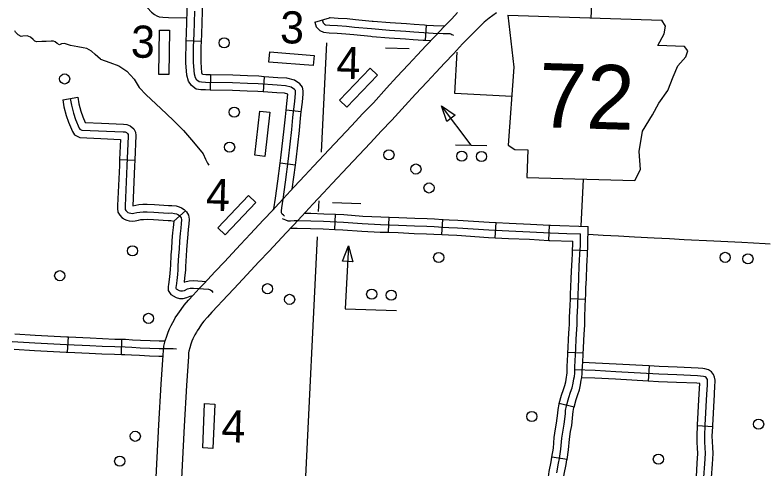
# Model space of a CAD drawing. Extents: x 653372 to 905732, y 627442 to 787275.
# Drawn here: x 676960 to 684356, y 769532 to 774006 of the extents above; entities that cross this region are included whole.
import ezdxf

# ---------------------------------------------------------------- set-up
doc = ezdxf.new("R2010")
doc.units = 0
for name, color, linetype in [('10', 7, 'Continuous'), ('21', 7, 'Continuous'), ('32', 7, 'Continuous'), ('33', 7, 'Continuous'), ('34', 7, 'Continuous'), ('35', 7, 'Continuous'), ('45', 7, 'Continuous'), ('5', 7, 'Continuous'), ('56', 7, 'Continuous'), ('6', 7, 'Continuous')]:
    doc.layers.add(name, color=color, linetype=linetype)

msp = doc.modelspace()

# ---------------------------------------------------------------- linework, layer by layer
at = {"layer": '10'}
for points in [[(678353, 769452.5), (678379.4, 769968.5), (678402.3, 770369), (678421, 770653.3), (678423.3, 770701.2), (678429.1, 770741), (678442, 770793.3), (678456.6, 770839.6), (678470.3, 770879.4), (678484.2, 770913), (678499.1, 770946.4), (678516.1, 770976.2), (678528.8, 770998.5), (678540.4, 771020.9), (678564.7, 771058.2), (678596.9, 771104), (678628.5, 771146.7), (678671.1, 771195.3), (678718.1, 771245.7), (678777.3, 771309.9), (678821.6, 771356.5), (678935.3, 771477.2), (679024.5, 771573.2), (679182.5, 771742.8), (679282.2, 771848.8), (679407.6, 771983.9), (679504.1, 772085.6), (679526.2, 772109.1), (679603.8, 772193.8), (679713.6, 772311.7), (679819.4, 772425), (679904.8, 772515.3), (680057.9, 772678.9), (680166.9, 772796), (680282.7, 772917.9), (680388.1, 773031.6), (680493.9, 773141.1), (680624, 773283.8), (680726.1, 773395.9), (680840.6, 773517.9), (680925.7, 773609.4), (681015.8, 773706.5), (681101.8, 773795.9), (681192.8, 773893.9), (681267.1, 773968.3), (681325, 774029.1)], [(681708.4, 774028.1), (681671.5, 774001.8), (681636.1, 773973.9), (681588.2, 773933.9), (681559.1, 773908.4), (681503, 773853.5), (681446, 773793.8), (681373, 773720.5), (681283.5, 773624.1), (681197.5, 773534.7), (681108.8, 773439.2), (681023.2, 773347.3), (680909.6, 773226.1), (680808.7, 773115.4), (680676.2, 772970), (680569.7, 772859.8), (680465, 772746.8), (680349, 772624.7), (680240.7, 772508.3), (680086.8, 772344), (680001.6, 772253.8), (679896.5, 772141.2), (679787.4, 772024.1), (679709.4, 771939), (679685.8, 771913.9), (679589.9, 771812.9), (679464.9, 771678.1), (679365, 771571.9), (679207.5, 771402.9), (679117.9, 771306.4), (679003.1, 771184.6), (678959.7, 771139), (678901.4, 771075.8), (678856.6, 771027.7), (678823.4, 770989.7), (678799.7, 770957.7), (678771.7, 770918), (678756.8, 770895), (678748.5, 770879.1), (678733.3, 770852.4), (678722.3, 770833.1), (678713.9, 770814.2), (678704.2, 770790.9), (678694, 770761.2), (678682.8, 770725.7), (678674.7, 770692.8), (678672.4, 770676.8), (678670.6, 770639.1), (678651.8, 770353.6), (678629, 769955), (678602.6, 769439.1)]]:
    msp.add_lwpolyline(points, dxfattribs=at)
at = {"layer": '21'}
for p, q in [((681819.5, 774002.5), (681880.4, 773492.9)), ((683373.5, 773896.6), (683340.2, 773956.1)), ((683362.8, 773820.8), (683373.5, 773896.6)), ((683300, 773704.2), (683362.8, 773820.8)), ((683562.1, 773696.3), (683300, 773704.2)), ((683594.7, 773653), (683562.1, 773696.3)), ((683497.1, 773503.6), (683576, 773594.4)), ((683576, 773594.4), (683594.7, 773653)), ((681880.4, 773492.9), (681823.5, 772724.5)), ((683451.5, 773395), (683497.1, 773503.6)), ((683396.7, 773261.2), (683451.5, 773395)), ((683308.4, 773136.9), (683396.7, 773261.2)), ((683245.6, 773020.3), (683308.4, 773136.9)), ((683147.8, 772862.5), (683245.6, 773020.3)), ((683116.3, 772660.3), (683147.8, 772862.5)), ((681823.5, 772724.5), (681889.8, 772680.2)), ((681889.8, 772680.2), (682016.7, 772676.4)), ((682016.7, 772676.4), (682008.5, 772405.9)), ((683127.9, 772482.3), (683116.3, 772660.3)), ((683073.9, 772373.9), (683127.9, 772482.3)), ((682008.5, 772405.9), (683073.9, 772373.9))]:
    msp.add_line(p, q, dxfattribs=at)
msp.add_lwpolyline([(681819.5, 774002.5), (683340.2, 773956.1)], dxfattribs=at)
at = {"layer": '32'}
for p, q in [((678798.9, 773745.3), (678649, 773751.6)), ((678886.7, 773416), (678883.5, 773266)), ((679418.1, 773397.3), (679407.4, 773247.7)), ((679782.9, 773052.8), (679633.8, 773069.2)), ((679724.5, 772526.4), (679575.8, 772546.1)), ((680114.7, 771892.3), (680122, 772042.1)), ((680642.9, 771864.4), (680648.2, 772014.3)), ((681168.3, 771842), (681177.7, 771991.7)), ((681696.1, 771810.6), (681704, 771960.4)), ((682223.1, 771784.7), (682231.7, 771934.5)), ((682607.7, 771681.5), (682457.9, 771689.4)), ((682586.8, 771201.2), (682436.9, 771207.4)), ((677479, 770683.4), (677486.2, 770833.3)), ((678008.4, 770661.4), (678011.9, 770811.4)), ((682562.9, 770673.5), (682413.1, 770680.3)), ((682472.9, 770141.1), (682327.7, 770178.6)), ((682403.5, 769625.4), (682255.3, 769648.8))]:
    msp.add_line(p, q, dxfattribs=at)
for points in [[(678649, 773751.6), (678652, 773822.6), (678658.3, 774045.4), (678661.5, 774150.2), (678666.5, 774279)], [(678798.9, 773745.3), (678802, 773817.3), (678808.3, 774041.1), (678811.4, 774145.1), (678816.4, 774273.3)], [(679725.4, 773261), (679717.5, 773271.3), (679683.7, 773293.4), (679628.5, 773308.2), (679545.6, 773313), (679358.9, 773326.4), (679251.2, 773331.2), (679105.5, 773336.3), (678839.1, 773342), (678800.4, 773343.2), (678777.2, 773347), (678753.7, 773364), (678738.8, 773385.4), (678729.1, 773423.7), (678720.8, 773536.5), (678720.4, 773601.8), (678721.6, 773693.3), (678727, 773819.9), (678733.3, 774043.3)], [(678883.5, 773266), (678837.2, 773267), (678793.1, 773268.3), (678747.6, 773275.8), (678699.4, 773310.7), (678669.4, 773353.8), (678654.7, 773411.7), (678645.8, 773533.6), (678645.4, 773602), (678646.7, 773695.4), (678649, 773751.6)], [(678886.7, 773416), (678841.1, 773417), (678807.9, 773418), (678803.4, 773435.8), (678795.8, 773539.5), (678795.4, 773601.5), (678796.6, 773691.2), (678798.9, 773745.3)], [(679418.1, 773397.3), (679363.3, 773401.3), (679254.2, 773406.1), (679107.6, 773411.3), (678886.7, 773416)], [(679782.9, 773052.8), (679793.4, 773147.9), (679801.8, 773228.1), (679802.8, 773259.2), (679794.8, 773293.7), (679769.3, 773327.1), (679714.6, 773362.7), (679640.5, 773382.6), (679550.4, 773387.9), (679418.1, 773397.3)], [(679407.4, 773247.7), (679354.6, 773251.5), (679248.2, 773256.2), (679103.3, 773261.4), (678883.5, 773266)], [(679633.8, 773069.2), (679644.3, 773164), (679650.6, 773224.6), (679616.4, 773233.8), (679540.7, 773238.2), (679407.4, 773247.7)], [(679617.8, 772024.1), (679606.8, 772033.1), (679596.1, 772044.4), (679589.1, 772057.2), (679586.5, 772077.2), (679590.5, 772104.9), (679602.8, 772191.5), (679626.5, 772357.9), (679657.1, 772588.6), (679689.8, 772876.9), (679701.1, 772995.2), (679718.8, 773156), (679726.9, 773233.1), (679727.5, 773251.8), (679725.4, 773261)], [(679575.8, 772546.1), (679582.7, 772597.7), (679615.2, 772884.7), (679626.5, 773002.9), (679633.8, 773069.2)], [(679724.5, 772526.4), (679731.5, 772579.4), (679764.4, 772869.1), (679775.7, 772987.6), (679782.9, 773052.8)], [(679513.4, 772095.2), (679528.6, 772202), (679552.2, 772368.1), (679575.8, 772546.1)], [(679693.1, 772289.8), (679724.5, 772526.4)], [(679814.8, 772053.6), (679877.9, 772052.6), (680004.5, 772047.8), (680122, 772042.1)], [(680122, 772042.1), (680203.5, 772038.2), (680389, 772024.4), (680567.8, 772017.2), (680648.2, 772014.3)], [(679594.9, 771999.8), (679626.1, 771986), (679649.7, 771978), (679676.2, 771978.1), (679712, 771980.7), (679745, 771979.7), (679875.9, 771977.6), (680001.3, 771972.9), (680198.9, 771963.3), (680384.7, 771949.5), (680564.9, 771942.2), (680742.5, 771936), (680899.8, 771928.5), (681021.6, 771924.9), (681094.5, 771921.7), (681178.6, 771916.5), (681238, 771912.9), (681322.2, 771909.4), (681632.3, 771889.1), (681830.8, 771878.6), (682038.5, 771870.5), (682237, 771859), (682402.9, 771853.1), (682536.9, 771850.9)], [(680648.2, 772014.3), (680745.6, 772010.9), (680902.7, 772003.5), (681024.3, 771999.8), (681098.4, 771996.6), (681177.7, 771991.7)], [(681177.7, 771991.7), (681183.2, 771991.3), (681241.8, 771987.8), (681326.2, 771984.3), (681636.8, 771964), (681704, 771960.4)], [(679678.9, 771906.6), (679743.3, 771904.7), (679873.9, 771902.6), (679998.1, 771898), (680114.7, 771892.3)], [(680114.7, 771892.3), (680194.3, 771888.4), (680380.4, 771874.6), (680562.1, 771867.3), (680642.9, 771864.4)], [(681704, 771960.4), (681834.3, 771953.5), (682042.1, 771945.4), (682231.7, 771934.5)], [(682231.7, 771934.5), (682240.5, 771934), (682612.8, 771920.7)], [(682610.2, 771727.8), (682610.4, 771733.1), (682612.8, 771920.7)], [(680642.9, 771864.4), (680739.4, 771861), (680896.9, 771853.6), (681018.8, 771849.9), (681090.5, 771846.8), (681168.3, 771842)], [(681168.3, 771842), (681174, 771841.6), (681234.2, 771837.9), (681318.2, 771834.5), (681627.9, 771814.2), (681696.1, 771810.6)], [(682387.6, 770075.6), (682389.7, 770108.3), (682398.6, 770153.2), (682420.4, 770237.7), (682438.5, 770290.5), (682453.4, 770333.3), (682464.1, 770376.8), (682471.1, 770420.8), (682477, 770444.6), (682479.4, 770477.4), (682479.7, 770509.5), (682481.2, 770538.5), (682487.1, 770657), (682489.9, 770719.5), (682494.5, 770810.6), (682500.8, 770911.3), (682503, 770952.6), (682504.3, 771026.9), (682509.1, 771138.7), (682514.1, 771258.6), (682515.8, 771316.8), (682520.5, 771410.8), (682524.8, 771538.3), (682527.7, 771587.1), (682531.1, 771651.9), (682535.5, 771735.6), (682536.9, 771850.9)], [(681696.1, 771810.6), (681827.4, 771803.6), (682034.9, 771795.6), (682223.1, 771784.7)], [(682223.1, 771784.7), (682233.5, 771784.1), (682462.5, 771776)], [(682436.9, 771207.4), (682439.1, 771261.2), (682440.9, 771319.8), (682445.6, 771413.9), (682449.9, 771541.8), (682452.8, 771591.3), (682456.2, 771655.9), (682462.5, 771776)], [(682586.8, 771201.2), (682589, 771255.9), (682590.8, 771313.8), (682595.5, 771407.6), (682599.8, 771534.8), (682602.6, 771583), (682606, 771648), (682610.2, 771727.8)], [(682413.1, 770680.3), (682415, 770723), (682419.6, 770814.8), (682426, 770915.6), (682428.1, 770955.2), (682429.3, 771029.1), (682434.2, 771141.9), (682436.9, 771207.4)], [(682562.9, 770673.5), (682564.8, 770715.9), (682569.4, 770806.3), (682575.7, 770906.9), (682578, 770950), (682579.3, 771024.6), (682584, 771135.5), (682586.8, 771201.2)], [(676959.7, 770862.3), (677159.6, 770850.8), (677472.1, 770834), (677486.2, 770833.3)], [(676931, 770788.9), (677155.5, 770776), (677468.3, 770759.1), (677696.1, 770748.1), (677818.2, 770741.7), (677943.2, 770738), (678045.7, 770735.6), (678113.5, 770731.5), (678192.7, 770727), (678290.3, 770722.7), (678380.5, 770720), (678520.6, 770719.2), (678551.9, 770716.9)], [(677486.2, 770833.3), (677699.8, 770823), (677821.3, 770816.6), (677945.2, 770812.9), (678011.9, 770811.4)], [(678011.9, 770811.4), (678048.8, 770810.5), (678117.9, 770806.3), (678196.4, 770801.9), (678293.1, 770797.7), (678381.8, 770795), (678442.3, 770794.7)], [(676951.1, 770712.6), (677151.3, 770701.1), (677464.5, 770684.1), (677479, 770683.4)], [(677479, 770683.4), (677692.3, 770673.2), (677815.1, 770666.8), (677941.2, 770663), (678008.4, 770661.4)], [(678008.4, 770661.4), (678042.5, 770660.6), (678109.2, 770656.6), (678189, 770652.1), (678287.5, 770647.8), (678379.1, 770645), (678420.4, 770644.8)], [(682327.7, 770178.6), (682348.5, 770259.2), (682367.6, 770315), (682381.4, 770354.7), (682390.5, 770391.6), (682397.5, 770435.7), (682402.6, 770456.4), (682404.4, 770480.5), (682404.7, 770511.8), (682406.3, 770542.4), (682412.2, 770660.5), (682413.1, 770680.3)], [(682472.9, 770141.1), (682492.3, 770216.2), (682509.4, 770266), (682525.4, 770312), (682537.7, 770361.9), (682544.6, 770405.9), (682551.3, 770432.8), (682554.3, 770474.4), (682554.6, 770507.1), (682556.1, 770534.7), (682562, 770653.4), (682562.9, 770673.5)], [(682255.3, 769648.8), (682269.3, 769737.6), (682278.4, 769843.1), (682291.1, 769926.7), (682301.5, 769984), (682312.9, 770082.4), (682315.2, 770118.1), (682325.4, 770169.9), (682327.7, 770178.6)], [(682403.5, 769625.4), (682418.3, 769719.5), (682427.4, 769825.4), (682439.1, 769902.1), (682449.9, 769961.9), (682462.3, 770068.9), (682464.3, 770098.5), (682471.8, 770136.5), (682472.9, 770141.1)], [(682302.4, 769493.9), (682320, 769589.6), (682329.3, 769636.4), (682343.8, 769728.5), (682352.9, 769834.3), (682365.1, 769914.4), (682375.7, 769973), (682387.6, 770075.6)], [(682255.8, 769095.3), (682241.9, 769143.6), (682229, 769213.9), (682221.6, 769278.4), (682217.7, 769320.2), (682215.5, 769350.7), (682214.3, 769383.1), (682215.4, 769420.9), (682220.9, 769455.5), (682228.4, 769506.2), (682246.3, 769603.6), (682255.4, 769649.5), (682255.3, 769648.8)], [(682399.9, 769136.8), (682388.1, 769178), (682377.4, 769236), (682370.8, 769293.7), (682367.2, 769332.5), (682365.3, 769359.1), (682364.3, 769383.7), (682365, 769406.7), (682369.2, 769432.7), (682376.4, 769481.6), (682393.7, 769575.5), (682403.1, 769623.3), (682403.5, 769625.4)]]:
    msp.add_lwpolyline(points, dxfattribs=at)
at = {"layer": '33'}
msp.add_lwpolyline([(682611.9, 771845.7), (682761, 771835.5), (682910.8, 771828.3), (683069.6, 771820.7), (683261.7, 771809.9), (683413.5, 771802.2), (683557.6, 771794.2), (683850.9, 771780.8), (684129.2, 771765.6), (684358.9, 771754.5), (684407.9, 771751.5)], dxfattribs=at)
at = {"layer": '34'}
for points in [[(682641.4, 773977.5), (682664.1, 774437), (682664.1, 774486.9), (682663.2, 774506.4)], [(682541.9, 771923.2), (682564.7, 772389.2)]]:
    msp.add_lwpolyline(points, dxfattribs=at)
at = {"layer": '35'}
for points in [[(677803.9, 773571.9), (677751.5, 773616), (677715.6, 773649.5), (677667.2, 773675.5), (677632.8, 773683.3), (677579.3, 773690.5), (677507, 773705), (677449.5, 773725.7), (677419.2, 773721), (677397.7, 773712.7), (677376.8, 773724.5), (677357.2, 773741.9), (677339.5, 773749.1), (677314.9, 773747.6), (677266.7, 773745.7), (677223, 773743.7), (677174.9, 773741.8), (677154.9, 773746.9), (677137.6, 773765.3), (677113.7, 773788.4), (677079.9, 773801.7), (677037.9, 773796.2), (677021, 773792.3), (676990.1, 773808.9), (676965.3, 773836.5), (676956.8, 773851.2)], [(677803.9, 773571.9), (677896.6, 773537.7), (677984.5, 773503.4), (678062.7, 773451.9), (678134, 773374.1), (678185.8, 773292.7), (678252.1, 773220.1), (678396.3, 773082.8), (678519.7, 772970.7), (678621.9, 772866.3), (678701, 772775), (678768, 772692.1), (678815.5, 772637.5), (678838.5, 772585.7), (678857.7, 772544.2), (678872.6, 772527.3)]]:
    msp.add_lwpolyline(points, dxfattribs=at)
at = {"layer": '45'}
for p, q in [((679917.2, 773935.7), (680061.2, 773977.9)), ((681009.4, 773756.3), (681017.9, 773906)), ((677430.5, 773168.8), (677578.2, 773194.7)), ((677991.5, 772582.2), (678141.4, 772575.6)), ((678526.7, 771975.5), (678641, 772074.7)), ((683212.9, 770547.8), (683204.9, 770398)), ((683840.5, 769948.8), (683690.6, 769955.7))]:
    msp.add_line(p, q, dxfattribs=at)
for points in [[(678188.8, 774154.7), (678203.8, 774141.2), (678232.8, 774112.9), (678267.9, 774075), (678306.9, 774034.4), (678336, 774011.8), (678358.1, 773998.4), (678382.7, 773987), (678418.4, 773983.6), (678473.4, 773982), (678656.4, 773976.5)], [(680060.3, 773980.9), (680068.4, 773980.1), (680145.3, 773976), (680235.4, 773970.2), (680316.6, 773961.6), (680480.8, 773945.8), (680493.4, 773944.7)], [(679917.2, 773935.7), (679930.8, 773889.4), (679967.3, 773852.3), (680002.2, 773835.5), (680057.7, 773830.5), (680136.4, 773826.3), (680222.6, 773820.7), (680301.5, 773812.4), (680467.3, 773796.4), (680480.8, 773795.2)], [(679989.2, 773956.8), (679997.5, 773928.6), (680011.6, 773914.2), (680022.4, 773909), (680063.1, 773905.3), (680140.8, 773901.2), (680229, 773895.5), (680309.1, 773887), (680474.1, 773871.1), (680653.7, 773855.9), (680815.2, 773845.6)], [(680493.4, 773944.7), (680659.2, 773930.7), (680820.2, 773920.4), (680897.9, 773915), (680996.7, 773907.2), (681017.9, 773906)], [(681017.9, 773906), (681086.6, 773902.1), (681197.4, 773898.8)], [(680815.2, 773845.6), (680892.3, 773840.2), (680991.6, 773832.4), (681083.3, 773827.2), (681183.6, 773824.2), (681248.7, 773822.2), (681257.7, 773820.8), (681267.9, 773814.4), (681282.9, 773807.2)], [(680480.8, 773795.2), (680648.2, 773781.1), (680810.2, 773770.8), (680886.8, 773765.5), (680986.5, 773757.6), (681009.4, 773756.3)], [(681009.4, 773756.3), (681060.9, 773753.4)], [(677430.5, 773168.8), (677442.5, 773099.9), (677464.6, 773015.4), (677487.4, 772949.2), (677526.4, 772857.9), (677547, 772823.2), (677598.3, 772797.2), (677804.9, 772788.3)], [(677504.3, 773181.7), (677515.9, 773115.8), (677536.4, 773037.2), (677557.4, 772976.2), (677593.4, 772891.9), (677600.3, 772880.2), (677617.7, 772871.4), (678028.1, 772853.9), (678046.8, 772853.3), (678058.1, 772848.8), (678070.3, 772839.1), (678074.2, 772829.6), (678076.8, 772812.9), (678063.8, 772518.8), (678046.3, 772125.4), (678045.6, 772102.5), (678047.7, 772087.9), (678053.2, 772077.8), (678062.2, 772068.7), (678072.9, 772061.1), (678086.8, 772056), (678100.7, 772051.4), (678116.8, 772049.9), (678132.5, 772051.5), (678160.7, 772057.9), (678191.6, 772064.3), (678225, 772065.9), (678263, 772067.4), (678329.7, 772063.8), (678470.9, 772054.4), (678502.7, 772055), (678532.7, 772050.4), (678553.3, 772045.1), (678564.6, 772039.6), (678580.4, 772029.2), (678590, 772019.6), (678598.4, 772005.3), (678601.6, 771988.5), (678599.4, 771952.2), (678593.8, 771904.5), (678588.1, 771852.1), (678581.2, 771778.4), (678577.2, 771697.4), (678572.3, 771636.7), (678567.1, 771532.7), (678564.9, 771495.8), (678561, 771450.1), (678555, 771389.4), (678547.7, 771338.1), (678544.7, 771323.1), (678544.8, 771314.5), (678548.9, 771307.8)], [(677578.2, 773194.7), (677589.2, 773131.8), (677608.2, 773058.9), (677627.5, 773003.2), (677652.3, 772945), (677811.3, 772938.2)], [(677811.3, 772938.2), (678030.8, 772928.8), (678062.3, 772927.9), (678096.2, 772914.4), (678132.3, 772885.5), (678146.9, 772849.9), (678152, 772817.1), (678141.4, 772575.6)], [(677804.9, 772788.3), (678000.3, 772780), (677991.5, 772582.2)], [(677991.5, 772582.2), (677988.9, 772522.1), (677971.3, 772128.2), (677970.4, 772098.1), (677975.5, 772063.9), (677992.3, 772032.6), (678013.6, 772011.3), (678028.6, 772000.6)], [(678141.4, 772575.6), (678138.7, 772515.5), (678121.4, 772126.4)], [(678121.4, 772126.4), (678182.2, 772138.9), (678221.7, 772140.8), (678263.5, 772142.4), (678334.2, 772138.7), (678472.7, 772129.4), (678507.6, 772130.1), (678547.7, 772124), (678579.5, 772115.8), (678601.8, 772104.8), (678628.1, 772087.6), (678641, 772074.7)], [(678641, 772074.7), (678649.9, 772065.7), (678669.7, 772032), (678677, 771993.3), (678674.2, 771945.6), (678668.4, 771896), (678662.7, 771844.5), (678656, 771773.1), (678652.1, 771692.5), (678647.1, 771631.7), (678642, 771528.6), (678640, 771494.5)], [(678028.6, 772000.6), (678037.7, 771994.2), (678062.2, 771985.2), (678085.3, 771977.6), (678117.1, 771974.5), (678144.7, 771977.4), (678176.6, 771984.6), (678201, 771989.7), (678228.2, 771991), (678262.4, 771992.3), (678325.2, 771988.9), (678469.1, 771979.3), (678497.7, 771979.9), (678526.7, 771975.5)], [(678526.7, 771975.5), (678519.3, 771912.9), (678513.5, 771859.7), (678506.4, 771783.8), (678502.4, 771702.3), (678497.4, 771641.6), (678492.2, 771536.7), (678490.2, 771503.2)], [(678490.2, 771503.2), (678490.1, 771501.2), (678486.3, 771457), (678480.5, 771398.4), (678473.8, 771350.9), (678469.5, 771330), (678470.2, 771292.4), (678495.8, 771251.4), (678550.6, 771221.5), (678582.9, 771213.4), (678617.6, 771212.7), (678655.2, 771220.9), (678685.9, 771235.1), (678715, 771242.5)], [(678640, 771494.5), (678639.7, 771490.4), (678635.6, 771443.2), (678629.5, 771380.5), (678628.5, 771373.8), (678635.6, 771377.1), (678676.4, 771387.4), (678721.9, 771388.7), (678843.7, 771380)], [(678548.9, 771307.8), (678578.1, 771291.9), (678592.9, 771288.2), (678610.3, 771287.9), (678631.2, 771292.4), (678660.7, 771306.1), (678686.8, 771312.7), (678720.3, 771313.7), (678866.5, 771303.1), (678888.2, 771297.3), (678899.4, 771287.5), (678912.3, 771270.5)], [(682685.7, 770576.1), (682684, 770576.2), (682558.4, 770581.3)], [(683212.9, 770547.8), (682889.4, 770565.2), (682685.7, 770576.1)], [(683766, 769963), (683783.2, 770268.7), (683788.1, 770359.2), (683789.5, 770389.6), (683789.9, 770401.8), (683787.6, 770413.7), (683783.1, 770424.5), (683776.4, 770433.2), (683766, 770439.9), (683749.6, 770444.7), (683690.1, 770451.2), (683486.5, 770459.5), (683310.2, 770467.5), (682885.4, 770490.3), (682680.4, 770501.3), (682479.7, 770509.5)], [(683744.4, 770520.7), (683695.7, 770526.1), (683489.7, 770534.4), (683313.9, 770542.4), (683212.9, 770547.8)], [(683840.5, 769948.8), (683841, 769959.1), (683858.1, 770264.6), (683863, 770355.4), (683864.5, 770386.7), (683865.1, 770408), (683859.7, 770435.4), (683848.6, 770462.2), (683828, 770489.2), (683797.3, 770508.9), (683764.3, 770518.5), (683744.4, 770520.7)], [(682677.6, 770426.3), (682676.9, 770426.4), (682551.2, 770431.5)], [(683204.9, 770398), (682881.4, 770415.5), (682677.7, 770426.3)], [(683713.7, 770373.2), (683684.4, 770376.4), (683483.3, 770384.6), (683306.5, 770392.5), (683204.9, 770398)], [(683690.6, 769955.7), (683691.1, 769966.8), (683708.3, 770272.8), (683713.7, 770373.2)], [(683678.7, 769427.3), (683679.5, 769453.7), (683687.8, 769588), (683693.8, 769685.3), (683691.5, 769739.1), (683687.7, 769793.3), (683686.3, 769860.6), (683690.6, 769955.7)], [(683770.4, 768899), (683760.3, 768972.6), (683751.2, 769042.7), (683743.9, 769102.7), (683742.7, 769132.1), (683744.7, 769199.2), (683750.5, 769322.4), (683754.4, 769450.3), (683762.6, 769583.4), (683768.9, 769684.5), (683766.4, 769743.3), (683762.7, 769796.7), (683761.3, 769859.7), (683766, 769963)], [(683828.6, 769422.8), (683829.3, 769446.8), (683837.5, 769578.8), (683844, 769683.8), (683841.3, 769747.5), (683837.6, 769800.1), (683836.4, 769858.8), (683840.5, 769948.8)]]:
    msp.add_lwpolyline(points, dxfattribs=at)
at = {"layer": '5'}
for points in [[(680031.8, 773730.9), (679979.3, 772652.6)], [(679956, 772174.2), (679950.9, 772070.5)], [(679938.6, 771818.6), (679817.1, 769322.4)]]:
    msp.add_lwpolyline(points, dxfattribs=at)
at = {"layer": '56'}
for p, q in [((681217.9, 772957.6), (681166.5, 773110.5)), ((681166.5, 773110.5), (681299.3, 773019.1)), ((681299.3, 773019.1), (681217.9, 772957.6)), ((680189.8, 771579.8), (680248.4, 771730)), ((680248.4, 771730), (680291.7, 771574.7)), ((680291.7, 771574.7), (680189.8, 771579.8))]:
    msp.add_line(p, q, dxfattribs=at)
for points in [[(678385, 773857.3), (678484.9, 773855.8), (678478.4, 773418.4), (678378.4, 773419.9)], [(679464.6, 773542.5), (679472.7, 773642.2), (679908.8, 773606.5), (679900.6, 773506.8)], [(680232, 773097.9), (680159.9, 773167.2), (680463.1, 773482.7), (680535.2, 773413.4)], [(679373.7, 773058.2), (679473, 773047), (679424, 772612.2), (679324.6, 772623.4)], [(679261, 772226.2), (679333.6, 772157.4), (679032.5, 771839.9), (678960, 771908.8)], [(678829.2, 770176.1), (678929.1, 770172), (678910.8, 769734.8), (678810.9, 769739)]]:
    msp.add_lwpolyline(points, close=True, dxfattribs=at)
for points in [[(680612.6, 773682.7), (680847.7, 773675.7)], [(681458.7, 772723.2), (681166.5, 773110.5)], [(681304.9, 772727.9), (681612.5, 772718.6)], [(680091.1, 772156.4), (680371, 772148)], [(680248.4, 771730), (680217.2, 771109.2), (680722, 771094.1)]]:
    msp.add_lwpolyline(points, dxfattribs=at)
for centre in [(679022.2, 773731.3), (677449.4, 773375.4), (679122.5, 773047.5), (679076.3, 772704), (680647.4, 772628.6), (681365.4, 772614.3), (681561.1, 772611.1), (680913.8, 772487.6), (681042.7, 772301.6), (678118, 771681), (681138, 771616.6), (683962.5, 771617.6), (684188.3, 771603.4), (677400.7, 771436.8), (679450.1, 771308.6), (680477.6, 771255.3), (679667.9, 771203.5), (680670.3, 771244.3), (678275.5, 771016.4), (682057, 770048.8), (684293, 769974.2), (678145.9, 769854.5), (683304.6, 769629.1), (677992.5, 769608.4)]:
    msp.add_circle(centre, 50, dxfattribs=at)
at = {"layer": '6'}
msp.add_lwpolyline([(681858.8, 773201.1), (681297.4, 773230.8), (681319.2, 773639.7), (681319.6, 773641)], dxfattribs=at)

# ---------------------------------------------------------------- texts
at = {"layer": '21'}
msp.add_text('72', height=633.6, rotation=358.28003, dxfattribs=at).set_placement((682117, 772901))
at = {"layer": '56'}
for s, p in [('3', (679570.8, 773729)), ('3', (678099.6, 773587.9)), ('4', (680125.3, 773378.6)), ('4', (678839.8, 772078.7)), ('4', (678992.4, 769797.9))]:
    msp.add_text(s, height=316.8, rotation=358.28003, dxfattribs=at).set_placement(p)

doc.saveas('drawing.dxf')
